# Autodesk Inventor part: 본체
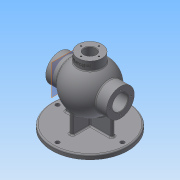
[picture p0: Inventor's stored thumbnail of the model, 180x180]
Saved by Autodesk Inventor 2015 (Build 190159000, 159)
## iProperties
Created: 2020-08
Part Number: 본체
Material: 일반
Document SubType Name: Modeling
Designer: user
Density: 1 g/cm^3
Appearance: 기본값
Author: user
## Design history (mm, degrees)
node "작업 평면4"
sketch "스케치7"
  geometry: C1 r 85 at (0, 0); 1 further point
  constraints: 1 centre point, 1 coincident
  dimensions: "d15" = 170 diameter of C1
sketch "스케치1"
  geometry: L1 (95.587, 0)-(-77.665, 0); A1 r 53 centre (0, 0) between (-53, 0) and (53, 0); A2 r 43 centre (0, 0) between (-43, 0) and (43, 0); 1 further point
  constraints: 4 point on circle, 4 point on line, 2 centre point, 2 coincident, 2 end point, 1 horizontal
  dimensions: "d0" = 106 diameter of A1
revolve "회전1" sketch "스케치1" stored, may be unused: angle "d3" = 90 deg
node "작업 평면2"
sketch "스케치3"
  geometry: C1 r 31 at (0, 0); 1 further point
  constraints: 1 centre point, 1 coincident
  dimensions: "d6" = 62 diameter of C1
extrude "돌출1" join sketch "스케치3" distance "d7" = 136; taper "d8" = 0 deg
extrude "돌출3" join sketch "스케치7" distance "d16" = 10; taper "d17" = 0 deg
sketch "스케치8"
  geometry: C1 r 85 at (0, 0) reference; A1 r 72.5 centre (0, 0) between (-72.5, 0) and (0, 72.5); 2 further points
  constraints: 4 point on circle, 1 centre point, 1 coincident
  dimensions: "d18" = 145 diameter of A1
hole "구멍1" sketch "스케치8" at (-72.5, 0), (0, 72.5), (72.5, 0), (0, -72.5) diameter "d19" = 9; stored, may be unused: countersink angle "d23" = 90 deg, drill point angle "d25" = 118 deg; dims "d20" = 6, "d21" = 4, "d22" = 2, "d24" = 9
fillet "모깎기1" dims "d26" = 3
node "작업 평면5"
sketch "스케치9"
  geometry: C1 r 27 at (0, 0); 1 further point
  constraints: 1 centre point, 1 coincident
  dimensions: "d28" = 54 diameter of C1
extrude "돌출4" join sketch "스케치9" distance "d29" = 65; taper "d30" = 0 deg
sketch "스케치10"
  geometry: L1 (0, 0)-(52, 0); L2 (52, 0)-(52, -85); L3 (52, -85)-(0, -85); L4 (0, -85)-(0, 0); L5 (0, 0)-(-52, 0); L6 (-52, 0)-(-52, -85); L7 (-52, -85)-(0, -85); L8 (0, -85)-(0, 0)
  constraints: 16 end point, 4 parallel, 2 horizontal, 2 perpendicular
  dimensions: "d31" = 52 distance of L2.end L3.end; "d32" = 85 distance of L1.end L2.end; "d33" = 52 distance of L7.end L6.end; "d34" = 85 distance of L6.end L5.end
extrude "돌출5" join sketch "스케치10" stored distance "d35" = 8; taper "d36" = 0 deg
sketch "스케치11"
  geometry: L1 (0, 0)-(-85, 0); L2 (-85, 0)-(-85, -43); L3 (-85, -43)-(0, -43); L4 (0, -43)-(0, 0); L5 (0, 0)-(-85, 0); L6 (-85, 0)-(-85, 43); L7 (-85, 43)-(0, 43); L8 (0, 43)-(0, 0)
  constraints: 16 end point, 4 parallel, 2 horizontal, 2 perpendicular
  dimensions: "d37" = 85 distance of L3.end L2.end; "d38" = 43 distance of L2.end L1.end; "d39" = 85 distance of L6.end L7.end; "d40" = 43 distance of L5.end L6.end
extrude "돌출6" join sketch "스케치11" stored distance "d41" = 8; taper "d42" = 0 deg
sketch "스케치12"
  geometry: C1 r 27 at (0, 0) reference; C2 r 13 at (0, 0)
  constraints: 1 centre point, 1 coincident
  dimensions: "d43" = 26 diameter of C2
extrude "돌출7" cut sketch "스케치12" distance "d44" = 65; taper "d45" = 0 deg
sketch "스케치13"
  geometry: C1 r 31 at (0, 0) reference; C2 r 17.5 at (0, 0)
  constraints: 1 centre point, 1 coincident
  dimensions: "d46" = 35 diameter of C2
extrude "돌출8" cut sketch "스케치13" stored distance "d47" = 65; taper "d48" = 0 deg
sketch "스케치14"
  geometry: L1 (0, 99.007)-(0, -122.152); A1 r 43 centre (0, 0) between (0, -43) and (0, 43); 1 further point
  constraints: 2 end point, 2 point on circle, 2 point on line, 1 centre point, 1 coincident, 1 vertical
  dimensions: "d49" = 86 diameter of A1
revolve "회전2" sketch "스케치14" stored, may be unused: angle "d50" = 90 deg
sketch "스케치15"
  geometry: C1 r 27 at (0, 0) reference; A1 r 20 centre (0, 0) between (-20, 0) and (0, -20); 2 further points
  constraints: 4 point on circle, 1 centre point, 1 coincident
  dimensions: "d51" = 40 diameter of A1
hole "구멍2" sketch "스케치15" at (-20, 0), (0, -20), (20, 0), (0, 20) diameter "d52" = 3.242; stored, may be unused: countersink angle "d56" = 90 deg, drill point angle "d58" = 118 deg; dims "d53" = 8, "d54" = 4, "d55" = 2, "d57" = 15
sketch "스케치16"
  geometry: C1 r 31 at (0, 0) reference; A1 r 24 centre (0, 0) between (0, 24) and (-24, 0); 2 further points
  constraints: 4 point on circle, 1 centre point, 1 coincident
  dimensions: "d59" = 48 diameter of A1
sketch "스케치17"
  geometry: C1 r 31 at (0, 0) reference; A1 r 24 centre (0, 0) between (0, 24) and (-24, 0); 2 further points
  constraints: 4 point on circle, 1 centre point, 1 coincident
  dimensions: "d60" = 48 diameter of A1
hole "구멍3" sketch "스케치17" at (0, 24), (24, 0), (0, -24), (-24, 0) diameter "d61" = 3.242; stored, may be unused: countersink angle "d65" = 90 deg, drill point angle "d67" = 118 deg; dims "d62" = 12, "d63" = 4, "d64" = 2, "d66" = 15
hole "구멍4" sketch "스케치16" diameter "d68" = 3.242; stored, may be unused: countersink angle "d72" = 90 deg, drill point angle "d74" = 118 deg; dims "d69" = 12, "d70" = 4, "d71" = 2, "d73" = 15
fillet "모깎기2" dims "d75" = 3
chamfer "모따기1" distance "d76" = 1; stored, may be unused: second distance "d77" = 2, angle "d78" = 45 deg
fillet "모깎기3" dims "d79" = 3
fillet "모깎기4" dims "d80" = 3
node "작업 평면6"
sketch "스케치18"
  geometry: L1 (0, 0)-(0, 56); L2 (-40.249, 68.099)-(41.063, 68.099); L3 (41.063, 68.099)-(41.063, 42.486); L4 (41.063, 42.486)-(-40.249, 42.486); L5 (-40.249, 42.486)-(-40.249, 68.099)
  constraints: 2 end point, 1 vertical, 2 other
  dimensions: "d82" = 56 distance of L1.start L1.end
feature "엠보싱1" sketch "스케치18" dims "d0" = 106, "d18" = 145, "d83" = 0.5, "d84" = 0
node "작업 평면7"
sketch "스케치19"
  geometry: C1 r 18.5 at (0, 0); 1 further point
  constraints: 1 centre point, 1 coincident
  dimensions: "d86" = 37 diameter of C1
extrude "돌출9" cut sketch "스케치19" distance "d87" = 1.75; taper "d88" = 0 deg
node "솔리드1"
other parameters: "d5" = 68, "d14" = -85, "d27" = 65, "d81" = 76.5, "d85" = -16
